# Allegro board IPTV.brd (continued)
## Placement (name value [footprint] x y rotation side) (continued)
R595  RC0402JR_070R  [R0402]  106.44 77.02 0 top
R596  RC0402JR_070R  [R0402]  106.44 78.17 0 top
R597  RC0402JR_070R  [R0402]  106.44 79.31 0 top
R598  RC0402JR_070R  [R0402]  106.44 80.45 0 top
R599  RC0402JR_070R  [R0402]  106.44 81.6 0 top
R600  RC0603JR_07510KL  [R0603]  91.07 78.93 180 top
R603  NI/RC0402JR_070R  [R0402]  156.19 54.24 180 top
R604  NI/RC0402JR_070R  [R0402]  156.19 52.97 180 top
R605  RCR0402JR_074K7  [R0402]  122.15 105.57 0 top
R606  RCR0402JR_074K7  [R0402]  122.15 104.43 0 top
R607  RHS_03K2490FT  [R0603]  128.27 101.73 0 top
R608  RCR0402JR_074K7  [R0402]  152.29 36.64 90 top
R609  RCR0402JR_074K7  [R0402]  153.68 36.64 90 top
R610  RHS_03K2490FT  [R0603]  156.06 45.76 0 top
R611  RCR0402JR_074K7  [R0402]  150.22 36.61 0 bottom
R612  RCR0402JR_074K7  [R0402]  153.39 34.07 90 bottom
R613  RHS_03K2490FT  [R0603]  144.76 32.8 180 bottom
R614  RCR0402JR_074K7  [R0402]  100.4 120.97 270 bottom
R615  RCR0402JR_074K7  [R0402]  99.25 120.97 270 bottom
R616  RHS_03K2490FT  [R0603]  96.62 118.66 90 top
R617  RK73B1ETTP330J  [R0402]  45.85 47.37 180 top
R618  RK73B1ETTP330J  [R0402]  30.58 40.93 0 bottom
R619  NC  [R0402]  36.84 20.25 270 bottom
R620  RC0402JR_070R  [R0402]  38.48 20.7 180 bottom
R621  NI/RC0402JR_070R  [R0402]  156.06 26.05 180 top
R622  RK73H1JTTD1001F  [R0603]  36.83 34.42 270 bottom
R623  RK73H1JTTD1001F  [R0603]  38.1 34.42 90 bottom
R624  RK73H1JTTD1001F  [R0603]  30.23 43.05 90 bottom
R625  RK73H1JTTD1001F  [R0603]  31.09 45.38 0 bottom
R626  NC  [R0402]  41.02 52.17 270 top
R627  NC  [R0402]  39.88 52.17 90 top
R628  NC  [R0402]  39.88 54.28 270 top
R629  NC  [R0402]  41.02 54.28 90 top
R630  NI/RC0402JR_070R  [R0402]  156.06 24.78 180 top
R631  RK73H1JTTD2000F  [R0603]  38.48 53.21 270 top
R632  NC/0R/0805  [R0805]  131.44 106.43 270 top
R633  NC/0R/0805  [R0805]  153.01 42.46 270 bottom
R634  RK73H1JTTD1001F  [R0603]  55.31 16.32 180 bottom
R635  RK73B1ETTP330J  [R0402]  43.92 6.26 0 bottom
R636  NC  [R0402]  37.85 25.65 270 bottom
R637  RC0402JR_070R  [R0402]  38.99 25.65 90 bottom
R638  RK73B1ETTP330J  [R0402]  38.48 19.43 0 bottom
R639  RK73H1JTTD1001F  [R0603]  51.85 5.27 180 bottom
R640  RK73H1JTTD1001F  [R0603]  51.85 6.54 0 bottom
R641  NC  [R0402]  42.16 21.97 0 top
R642  NC  [R0402]  42.16 20.83 180 top
R643  NC  [R0402]  40.13 20.83 0 top
R644  NC  [R0402]  40.13 21.97 180 top
R645  RK73H1JTTD2000F  [R0603]  41.15 19.56 0 top
R646  RK73H1JTTD1001F  [R0603]  55.31 17.59 0 bottom
R647  RC0603JR_0747K  [R0603]  38.23 21.97 0 bottom
R648  RC0603JR_0739K  [R0603]  38.23 23.62 0 bottom
R649  NC/0R/0805  [R0805]  148.82 34.2 0 top
R650  NC/0R/0805  [R0805]  99.54 117.64 180 bottom
REF*  VAL*  [unnamed#2]  160 102 0 top
REF*#2  VAL*  [unnamed#2]  9 102 0 top
REF*#3  VAL*  [unnamed#2]  160 12 0 top
REF*#4  VAL*  [unnamed#2]  9 12 0 top
T2  MMBT2222A  [SOT23_2]  99.72 91.75 90 top
T3  MMBT2222A  [SOT23_2]  107.29 12.86 270 top
T4  MMBT2222A  [SOT23_2]  123.44 9.65 180 top
T5  MMBT2222A  [SOT23_2]  127.36 9.94 0 bottom
T6  MMBT2222A  [SOT23_2]  99.92 12.74 270 top
T7  MMBT2222A  [SOT23_2]  9.75 59.47 90 top
T8  MMBT2222A  [SOT23_2]  109.32 92.87 270 bottom
T9  MMBT2222A  [SOT23_2]  14.96 32.3 0 bottom
TP1  -  [TP_SMD]  94.72 49.19 0 top
TP6  -  [TP_SMD]  135.36 90.08 0 top
TP7  -  [TP_SMD]  148.84 91.95 0 top
TP10  -  [TP_050M]  56.74 70.4 90 top
TP11  -  [TP_050M]  45.06 67.22 0 top
TP16  -  [TP_SMD]  128.14 79.88 0 top
TP19  -  [TP_SMD]  76.68 5.88 0 top
TP20  -  [TP_SMD]  77.45 10.32 0 top
TP29  -  [TP_SMD]  19.91 74.08 0 top
TP30  -  [TP_25]  90.02 101.38 0 top
TP31  -  [TP_25]  91.29 101.38 0 top
TP33  -  [TP_25]  30.58 84.62 0 top
TR2  H1606DG  [DIP-16]  23.37 100.71 270 top
U1  UPD720114GA_9BU_A  [QFP-9X9-48P-0_5S1]  98.56 77.91 270 top
U2  30M/3225  [OSC-3_2X2_5-4P]  88.15 75.88 270 top
U3  SRV05-4TCT  [SOT-23-6P]  116.46 113.28 90 bottom
U4  SRV05-4TCT  [SOT-23-6P]  159.11 38.77 0 bottom
U5  MIC2544_2BMMTR  [SO-4_9X3-8P-0_65]  126.75 104.39 180 top
U6  MIC2544_2BMMTR  [SO-4_9X3-8P-0_65]  153.81 41.72 270 top
U7  MIC2544_2BMMTR  [SO-4_9X3-8P-0_65]  149.43 34.16 0 bottom
U8  MIC2544_2BMMTR  [SO-4_9X3-8P-0_65]  99.16 118.91 90 top
U9  H5TQ1G63BFR_H9C  [CSP-14X10-96P-0_8]  37.72 41.4 90 top
U10  H5TQ1G63BFR_H9C  [CSP-14X10-96P-0_8]  48.51 11.81 180 top
U11  W25X16AVSSIG  [SO-7_9X5_2-8P-1_27]  91.82 55.12 270 top
U12  SIMMM12S2  [XS_SD_2041353_4]  26.95 36.12 270 top
U13  LM1117-ADJ  [SOT-223-4P]  53.57 73.82 90 top
U14  SRV05-4TCT  [SOT-23-6P]  47.24 110.74 180 bottom
U15  AZ1045-04F  [DFN-2_5X1-10P-0_5]  40.51 111.89 270 bottom
U16  AZ1045-04F  [DFN-2_5X1-10P-0_5]  42.16 115.06 0 bottom
U17  SRV05-4TCT  [SOT-23-6P]  23.62 92.2 90 bottom
U18  U/BCM43217KMLG/QFN68  [QFN-8X8-69P-0_4]  123.64 45.61 270 top
U19  U/RTC6603/SC70-6  [SC70-6P]  121.26 30.14 90 top
U20  SG809 2.63V  [SOT-23-3P]  74.52 11.21 0 top
U21  U/RTC6603/SC70-6  [SC70-6P]  130.91 30.39 180 top
U22  SGM8903  [SO-6_3X5-14P-0_65]  70.27 103.67 0 top
U23  U/PAM2305CGFADJ/PAM/QFN3X3  [DFN-2X2-7P-0_65S1]  112.66 41.03 270 bottom
U24  U/RT9166-12GVL/SOT23-3  [SOT-23-3P]  136.88 55.79 270 top
XL1  JA54-24MHZ(S)  [XL_HC_49U]  83.92 16.17 0 top
XP1  HDMI-SMT  [XP_HDMI_SMT]  40 119.4 180 top
XP2  TH-CNT-SX2.5-2P  [XP_2X1_100]  154.81 97.16 270 top
XS1  1064-00444  [USB-11153S1-13_6X14]  166.6 53.57 270 top
XS2  DC-2.0  [XS_DC_2_0]  144.5 117.79 270 top
XS4  1064-00444  [XS_USB_AF_4P]  108 116.3 270 top
XS5  1064-00444  [XS_USB_AF_4P]  125 116.3 270 top
XS7  DLT1150  [XS_DLT1150]  26.63 120.19 0 top
XS9  RCA-314-110  [XS_AV3_RCA_314]  91.25 118.4 180 top
XS10  1064-00444  [USB-11153S1-13_6X14]  166.6 25.42 270 top
XS11  <Value>  [RJ45-17_6X15-8PS1]  13.78 122.53 0 top
Y4  XTAL/20MHz/10ppm/8Z20070010  [OSC-3_2X2_5-4P]  136.12 44.11 90 top

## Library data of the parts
ANT1-ANT4 = ANT_0
ANT5 ANT6 = ANT_1
C1-C17 C19-C25 C35 C38-C42 C56-C59 C61 C67 C106 C122 C125 C128 C130-C133 C135 C138 C139 C142 C145 C147 C150 C154-C159 C162 C173 C175 C177 C180 C186 C196 C198 C200 C201 C275-C296 C298-C306 C309-C315 C392 C394 C404-C424 C426 C427 C429-C431 C433-C435 C437-C439 C441-C497 C0603 = C_0402
C18 = C_1206
C26 C28 C30 C31 C48 C63 C72 C178 C197 C199 = C_0805
C27 C29 = C_1210
C32 C33 C36 C37 C47 = CAPACITOR POL_0
C34 C60 C62 C268 C393 = C
C43-C46 C49-C52 C77-C82 C84-C98 C100 C102 C107-C109 C111-C121 C123 C124 C127 C134 C136 C137 C143 C144 C146 C148 C149 C151-C153 C160 C161 C163 C165 C167 C169 C171 C174 C176 C181 C182 C202 C205 C207-C209 C212-C217 C219-C223 C225-C227 C229-C237 C239 C243 C247 C251 C255 C297 C308 C341 C347-C354 C380-C384 = C_0603
C53 = C_2
C75 = C_0
C110 C126 C346 C425 C428 C432 C436 = CAP-X1
C193 C194 C224 C228 C238 C240-C242 C244-C246 C248-C250 C254 C316-C337 C339 C340 C342-C344 C355-C361 C364-C368 C370-C379 C385-C390 = CAP NP_5
C203 = CP_0
C210 C211 = 100nF_0402
C218 C345 C362 C363 C369 = CAP NP_0
C272 C274 = CAPACITOR NON-POL
C307 CAP3 = CAP_X
C338 C391 = C_1
D5 D6 = D_A_0
D10 D11 L23 R4-R6 R8-R10 R12 R15 R19 R28 R36-R87 R89 R91-R100 R102-R110 R112-R132 R134 R135 R138-R155 R157 R163-R173 R176-R178 R253-R255 R271 R273 R276 R290 R298-R316 R322 R329-R331 R354 R355 R365 R367 R368 R410 R414 R457 R458 R472-R475 R509 R563 R567 R583-R600 R603-R616 R621 R630 R632 R633 R649 R650 = R_0603
D16 = BAV99
D20 = BAV99_0
D37 = TSOP34338
FB1-FB4 L11 L12 L14 L15 L19 L25 L29 = L_0805
IC2 = NAND01GW3B2CN5E
IC5 IC26 = SOP14_065_440_640M_EXP
IC8 = IC12
IC9 = NCS2553DG
IC12 IC14 = MP1482DS
IC13 = HI3716C
IC17 = MP1484EN-LF-Z
JP1 = CN_5P-1_3
L1-L3 L5-L8 L10 L16 L18 L20-L22 L24 L34-L38 L41 L45 L46 = L_0603
L26 L31 L39 L40 L42 L44 = IND_1
L43 = INDUCTOR IRON
L47-L51 L55-L57 = L_0402
LED1 = LED_0805
LED5 LED12 = LED_0603
LED8 = LED_D4_2-2_54
LED10 LED11 = 209SURSYGW-S530
MARK1-MARK6 = MARK
Q5-Q10 = PWRMOSFET_EP_DGS_0
R7 R16 R18 R88 R90 R136 R137 R257 R317 R358 R359 R361 = R
R17 R133 R175 R188-R221 R231 R259-R270 R272 R274 R275 R277-R289 R360 R362 R617-R620 R622-R629 R631 R634-R648 = R_0402
R20 R29 R174 R252 R256 R318-R321 R323-R328 R332-R353 R356 R357 R397 = R_0
R101 R111 R160 R222-R230 R232 R233 R237 R240-R242 R244 R245 R248-R251 R292-R297 R363 R364 R366 R479 R485 = R_0805
R186 R187 = RESISTOR SIP 2
R234-R236 R238 R239 = R_0805: signal model: RESISTOR_SMD_RC0S00108_R0603_SB__
R246 = R_2
R247 = R_1
R258 = R_7
T2-T9 = MMBT2222A
TP1 TP6 TP7 TP10 TP11 TP16 TP19 TP20 TP29 = TP_30
TP30 TP31 TP33 = TP_25
TR2 = TR1
U1 = UPD720114GA_9BU_A
U2 = Q22FA2380008201
U3 U4 U14 U17 = SRV05-4TCT_1
U5-U8 = MIC2544_2BMMTR
U9 U10 = H5TQ1G63BFR_H9C
U11 = TMP75_1
U12 = SIMMM12S2_0
U13 = LM1117
U15 U16 = AZ1045-04F
U18 = U/BCM43217KMLG/QFN68_0
U19 U21 = U/RTC6603/SC70-6_1
U20 = ADM809_3
U22 = SGM8903_0
U23 = U/PAM2305CGFADJ/PAM/QFN3X3
U24 = U/RT9166-12GVL/SOT23-3
XL1 = XM/SM
XP1 = HDMI-SMT
XP2 = CN_2P-5A
XS1 = 1064-00444_0
XS2 = CN_3P-2_0
XS4 XS5 = 1064-00444
XS7 = DLT1150
XS9 = RCA-314-110
XS10 = 1064-00444_1
XS11 = RJ45_15X13-8PS1
Y4 = CRYSTAL_GND_1

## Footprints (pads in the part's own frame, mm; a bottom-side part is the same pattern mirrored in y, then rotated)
ANT-34X5-2P
  round 1.702 hole 1.092: 1(-10.162,0.182)
  oval 2.362x1.27 hole 1.6x0.508: 2(10.438,0.182)
BGA756_080M_38X38
  round 0.4 smd: A1(-14.8,14.8) A2(-14,14.8) A4(-12.4,14.8) A5(-11.6,14.8) A7(-10,14.8) A8(-9.2,14.8) A10(-7.6,14.8) A11(-6.8,14.8) A13(-5.2,14.8) A14(-4.4,14.8) A16(-2.8,14.8) A17(-2,14.8) A19(-0.4,14.8) A20(0.4,14.8) A22(2,14.8) A23(2.8,14.8) A25(4.4,14.8) A26(5.2,14.8) A28(6.8,14.8) A29(7.6,14.8) A31(9.2,14.8) A32(10,14.8) A34(11.6,14.8) A35(12.4,14.8) A37(14,14.8) A38(14.8,14.8) AA3(-13.2,-1.2) AA4(-12.4,-1.2) AA10(-7.6,-1.2) AA11(-6.8,-1.2) AA14(-4.4,-1.2) AA15(-3.6,-1.2) AA16(-2.8,-1.2) AA17(-2,-1.2) AA18(-1.2,-1.2) AA19(-0.4,-1.2) AA20(0.4,-1.2) AA21(1.2,-1.2) AA22(2,-1.2) AA23(2.8,-1.2) AA24(3.6,-1.2) AA25(4.4,-1.2) AA28(6.8,-1.2) AA29(7.6,-1.2) AA35(12.4,-1.2) AA36(13.2,-1.2) AB1(-14.8,-2) AB2(-14,-2) AB3(-13.2,-2) AB4(-12.4,-2) AB10(-7.6,-2) AB11(-6.8,-2) AB14(-4.4,-2) AB15(-3.6,-2) AB16(-2.8,-2) AB17(-2,-2) AB18(-1.2,-2) AB19(-0.4,-2) AB20(0.4,-2) AB21(1.2,-2) AB22(2,-2) AB23(2.8,-2) AB24(3.6,-2) AB25(4.4,-2) AB28(6.8,-2) AB29(7.6,-2) AB35(12.4,-2) AB36(13.2,-2) AB37(14,-2) AB38(14.8,-2) AC1(-14.8,-2.8) AC2(-14,-2.8) AC3(-13.2,-2.8) AC4(-12.4,-2.8) AC10(-7.6,-2.8) AC11(-6.8,-2.8) AC14(-4.4,-2.8) AC15(-3.6,-2.8) AC16(-2.8,-2.8) AC17(-2,-2.8) AC18(-1.2,-2.8) AC19(-0.4,-2.8) AC20(0.4,-2.8) AC21(1.2,-2.8) AC22(2,-2.8) AC23(2.8,-2.8) AC24(3.6,-2.8) AC25(4.4,-2.8) AC28(6.8,-2.8) AC29(7.6,-2.8) AC35(12.4,-2.8) AC36(13.2,-2.8) AC37(14,-2.8) AC38(14.8,-2.8) AD3(-13.2,-3.6) AD4(-12.4,-3.6) AD10(-7.6,-3.6) AD11(-6.8,-3.6) AD14(-4.4,-3.6) AD15(-3.6,-3.6) AD16(-2.8,-3.6) AD17(-2,-3.6) AD18(-1.2,-3.6) AD19(-0.4,-3.6) AD20(0.4,-3.6) AD21(1.2,-3.6) AD22(2,-3.6) AD23(2.8,-3.6) AD24(3.6,-3.6) AD25(4.4,-3.6) AD28(6.8,-3.6) AD29(7.6,-3.6) AD35(12.4,-3.6) AD36(13.2,-3.6) AE1(-14.8,-4.4) AE2(-14,-4.4) AE3(-13.2,-4.4) AE4(-12.4,-4.4) AE10(-7.6,-4.4) AE11(-6.8,-4.4) AE14(-4.4,-4.4) AE15(-3.6,-4.4) AE16(-2.8,-4.4) AE17(-2,-4.4) AE18(-1.2,-4.4) AE19(-0.4,-4.4) AE20(0.4,-4.4) AE21(1.2,-4.4) AE22(2,-4.4) AE23(2.8,-4.4) AE24(3.6,-4.4) AE25(4.4,-4.4) AE28(6.8,-4.4) AE29(7.6,-4.4) AE35(12.4,-4.4) AE36(13.2,-4.4) AE37(14,-4.4) AE38(14.8,-4.4) AF1(-14.8,-5.2) AF2(-14,-5.2) AF3(-13.2,-5.2) AF4(-12.4,-5.2) AF10(-7.6,-5.2) AF11(-6.8,-5.2) AF28(6.8,-5.2) AF29(7.6,-5.2) AF35(12.4,-5.2) AF36(13.2,-5.2) AF37(14,-5.2) AF38(14.8,-5.2) AG3(-13.2,-6) AG4(-12.4,-6) AG10(-7.6,-6) AG11(-6.8,-6) AG28(6.8,-6) AG29(7.6,-6) AG35(12.4,-6) AG36(13.2,-6) AH1(-14.8,-6.8) AH2(-14,-6.8) AH3(-13.2,-6.8) AH4(-12.4,-6.8) AH10(-7.6,-6.8) AH11(-6.8,-6.8) AH12(-6,-6.8) AH13(-5.2,-6.8) AH14(-4.4,-6.8) AH15(-3.6,-6.8) AH16(-2.8,-6.8) AH17(-2,-6.8) AH18(-1.2,-6.8) AH19(-0.4,-6.8) AH20(0.4,-6.8) AH21(1.2,-6.8) AH22(2,-6.8) AH23(2.8,-6.8) AH24(3.6,-6.8) AH25(4.4,-6.8) AH26(5.2,-6.8) AH27(6,-6.8) AH28(6.8,-6.8) AH29(7.6,-6.8) AH35(12.4,-6.8) AH36(13.2,-6.8) AH37(14,-6.8) AH38(14.8,-6.8) AJ1(-14.8,-7.6) AJ2(-14,-7.6) AJ3(-13.2,-7.6) AJ4(-12.4,-7.6) AJ10(-7.6,-7.6) AJ11(-6.8,-7.6) AJ12(-6,-7.6) AJ13(-5.2,-7.6) AJ14(-4.4,-7.6) AJ15(-3.6,-7.6) AJ16(-2.8,-7.6) AJ17(-2,-7.6) AJ18(-1.2,-7.6) AJ19(-0.4,-7.6) AJ20(0.4,-7.6) AJ21(1.2,-7.6) AJ22(2,-7.6) AJ23(2.8,-7.6) AJ24(3.6,-7.6) AJ25(4.4,-7.6) AJ26(5.2,-7.6) AJ27(6,-7.6) AJ28(6.8,-7.6) AJ29(7.6,-7.6) AJ35(12.4,-7.6) AJ36(13.2,-7.6) AJ37(14,-7.6) AJ38(14.8,-7.6) AK3(-13.2,-8.4) AK4(-12.4,-8.4) AK35(12.4,-8.4) AK36(13.2,-8.4) AL1(-14.8,-9.2) AL2(-14,-9.2) AL3(-13.2,-9.2) AL4(-12.4,-9.2) AL35(12.4,-9.2) AL36(13.2,-9.2) AL37(14,-9.2) AL38(14.8,-9.2) AM1(-14.8,-10) AM2(-14,-10) AM3(-13.2,-10) AM4(-12.4,-10) AM35(12.4,-10) AM36(13.2,-10) AM37(14,-10) AM38(14.8,-10) AN3(-13.2,-10.8) AN4(-12.4,-10.8) AN5(-11.6,-10.8) AN34(11.6,-10.8) AN35(12.4,-10.8) AN36(13.2,-10.8) AP1(-14.8,-11.6) AP2(-14,-11.6) AP3(-13.2,-11.6) AP4(-12.4,-11.6) AP5(-11.6,-11.6) AP6(-10.8,-11.6) AP33(10.8,-11.6) AP34(11.6,-11.6) AP35(12.4,-11.6) AP36(13.2,-11.6) AP37(14,-11.6) AP38(14.8,-11.6) AR1(-14.8,-12.4) AR2(-14,-12.4) AR3(-13.2,-12.4) AR4(-12.4,-12.4) AR5(-11.6,-12.4) AR6(-10.8,-12.4) AR7(-10,-12.4) AR8(-9.2,-12.4) AR9(-8.4,-12.4) AR10(-7.6,-12.4) AR11(-6.8,-12.4) AR12(-6,-12.4) AR13(-5.2,-12.4) AR14(-4.4,-12.4) AR15(-3.6,-12.4) AR16(-2.8,-12.4) AR17(-2,-12.4) AR18(-1.2,-12.4) AR19(-0.4,-12.4) AR20(0.4,-12.4) AR21(1.2,-12.4) AR22(2,-12.4) AR23(2.8,-12.4) AR24(3.6,-12.4) AR25(4.4,-12.4) AR26(5.2,-12.4) AR27(6,-12.4) AR28(6.8,-12.4) AR29(7.6,-12.4) AR30(8.4,-12.4) AR31(9.2,-12.4) AR32(10,-12.4) AR33(10.8,-12.4) AR34(11.6,-12.4) AR35(12.4,-12.4) AR36(13.2,-12.4) AR37(14,-12.4) AR38(14.8,-12.4) AT2(-14,-13.2) AT3(-13.2,-13.2) AT4(-12.4,-13.2) AT5(-11.6,-13.2) AT6(-10.8,-13.2) AT7(-10,-13.2) AT8(-9.2,-13.2) AT9(-8.4,-13.2) AT10(-7.6,-13.2) AT11(-6.8,-13.2) AT12(-6,-13.2) AT13(-5.2,-13.2) AT14(-4.4,-13.2) AT15(-3.6,-13.2) AT16(-2.8,-13.2) AT17(-2,-13.2) AT18(-1.2,-13.2) AT19(-0.4,-13.2) AT20(0.4,-13.2) AT21(1.2,-13.2) AT22(2,-13.2) AT23(2.8,-13.2) AT24(3.6,-13.2) AT25(4.4,-13.2) AT26(5.2,-13.2) AT27(6,-13.2) AT28(6.8,-13.2) AT29(7.6,-13.2) AT30(8.4,-13.2) AT31(9.2,-13.2) AT32(10,-13.2) AT33(10.8,-13.2) AT34(11.6,-13.2) AT35(12.4,-13.2) AT36(13.2,-13.2) AT37(14,-13.2) AU1(-14.8,-14) AU2(-14,-14) AU3(-13.2,-14) AU4(-12.4,-14) AU5(-11.6,-14) AU7(-10,-14) AU8(-9.2,-14) AU10(-7.6,-14) AU11(-6.8,-14) AU13(-5.2,-14) AU14(-4.4,-14) AU16(-2.8,-14) AU17(-2,-14) AU19(-0.4,-14) AU20(0.4,-14) AU22(2,-14) AU23(2.8,-14) AU25(4.4,-14) AU26(5.2,-14) AU28(6.8,-14) AU29(7.6,-14) AU31(9.2,-14) AU32(10,-14) AU34(11.6,-14) AU35(12.4,-14) AU36(13.2,-14) AU37(14,-14) AU38(14.8,-14) AV1(-14.8,-14.8) AV2(-14,-14.8) AV4(-12.4,-14.8) AV5(-11.6,-14.8) AV7(-10,-14.8) AV8(-9.2,-14.8) AV10(-7.6,-14.8) AV11(-6.8,-14.8) AV13(-5.2,-14.8) AV14(-4.4,-14.8) AV16(-2.8,-14.8) AV17(-2,-14.8) AV19(-0.4,-14.8) AV20(0.4,-14.8) AV22(2,-14.8) AV23(2.8,-14.8) AV25(4.4,-14.8) AV26(5.2,-14.8) AV28(6.8,-14.8) AV29(7.6,-14.8) AV31(9.2,-14.8) AV32(10,-14.8) AV34(11.6,-14.8) AV35(12.4,-14.8) AV37(14,-14.8) AV38(14.8,-14.8) B1(-14.8,14) B2(-14,14) B3(-13.2,14) B4(-12.4,14) B5(-11.6,14) B7(-10,14) B8(-9.2,14) B10(-7.6,14) B11(-6.8,14) B13(-5.2,14) B14(-4.4,14) B16(-2.8,14) B17(-2,14) B19(-0.4,14) B20(0.4,14) B22(2,14) B23(2.8,14) B25(4.4,14) B26(5.2,14) B28(6.8,14) B29(7.6,14) B31(9.2,14) B32(10,14) B34(11.6,14) B35(12.4,14) B36(13.2,14) B37(14,14) B38(14.8,14) C2(-14,13.2) C3(-13.2,13.2) C4(-12.4,13.2) C5(-11.6,13.2) C6(-10.8,13.2) C7(-10,13.2) C8(-9.2,13.2) C9(-8.4,13.2) C10(-7.6,13.2) C11(-6.8,13.2) C12(-6,13.2) C13(-5.2,13.2) C14(-4.4,13.2) C15(-3.6,13.2) C16(-2.8,13.2) C17(-2,13.2) C18(-1.2,13.2) C19(-0.4,13.2) C20(0.4,13.2) C21(1.2,13.2) C22(2,13.2) C23(2.8,13.2) C24(3.6,13.2) C25(4.4,13.2) C26(5.2,13.2) C27(6,13.2) C28(6.8,13.2) C29(7.6,13.2) C30(8.4,13.2) C31(9.2,13.2) C32(10,13.2) C33(10.8,13.2) C34(11.6,13.2) C35(12.4,13.2) C36(13.2,13.2) C37(14,13.2) D1(-14.8,12.4) D2(-14,12.4) D3(-13.2,12.4) D4(-12.4,12.4) D5(-11.6,12.4) D6(-10.8,12.4) D7(-10,12.4) D8(-9.2,12.4) D9(-8.4,12.4) D10(-7.6,12.4) D11(-6.8,12.4) D12(-6,12.4) D13(-5.2,12.4) D14(-4.4,12.4) D15(-3.6,12.4) D16(-2.8,12.4) D17(-2,12.4) D18(-1.2,12.4) D19(-0.4,12.4) D20(0.4,12.4) D21(1.2,12.4) D22(2,12.4) D23(2.8,12.4) D24(3.6,12.4) D25(4.4,12.4) D26(5.2,12.4) D27(6,12.4) D28(6.8,12.4) D29(7.6,12.4) D30(8.4,12.4) D31(9.2,12.4) D32(10,12.4) D33(10.8,12.4) D34(11.6,12.4) D35(12.4,12.4) D36(13.2,12.4) D37(14,12.4) D38(14.8,12.4) E1(-14.8,11.6) E2(-14,11.6) E3(-13.2,11.6) E4(-12.4,11.6) E5(-11.6,11.6) E6(-10.8,11.6) E33(10.8,11.6) E34(11.6,11.6) E35(12.4,11.6) E36(13.2,11.6) E37(14,11.6) E38(14.8,11.6) F3(-13.2,10.8) F4(-12.4,10.8) F5(-11.6,10.8) F34(11.6,10.8) F35(12.4,10.8) F36(13.2,10.8) G1(-14.8,10) G2(-14,10) G3(-13.2,10) G4(-12.4,10) G35(12.4,10) G36(13.2,10) G37(14,10) G38(14.8,10) H1(-14.8,9.2) H2(-14,9.2) H3(-13.2,9.2) H4(-12.4,9.2) H35(12.4,9.2) H36(13.2,9.2) H37(14,9.2) H38(14.8,9.2) J3(-13.2,8.4) J4(-12.4,8.4) J35(12.4,8.4) J36(13.2,8.4) K1(-14.8,7.6) K2(-14,7.6) K3(-13.2,7.6) K4(-12.4,7.6) K10(-7.6,7.6) K11(-6.8,7.6) K12(-6,7.6) K13(-5.2,7.6) K14(-4.4,7.6) K15(-3.6,7.6) K16(-2.8,7.6) K17(-2,7.6) K18(-1.2,7.6) K19(-0.4,7.6) K20(0.4,7.6) K21(1.2,7.6) K22(2,7.6) K23(2.8,7.6) K24(3.6,7.6) K25(4.4,7.6) K26(5.2,7.6) K27(6,7.6) K28(6.8,7.6) K29(7.6,7.6) K35(12.4,7.6) K36(13.2,7.6) K37(14,7.6) K38(14.8,7.6) L1(-14.8,6.8) L2(-14,6.8) L3(-13.2,6.8) L4(-12.4,6.8) L10(-7.6,6.8) L11(-6.8,6.8) L12(-6,6.8) L13(-5.2,6.8) L14(-4.4,6.8) L15(-3.6,6.8) L16(-2.8,6.8) L17(-2,6.8) L18(-1.2,6.8) L19(-0.4,6.8) L20(0.4,6.8) L21(1.2,6.8) L22(2,6.8) L23(2.8,6.8) L24(3.6,6.8) L25(4.4,6.8) L26(5.2,6.8) L27(6,6.8) L28(6.8,6.8) L29(7.6,6.8) L35(12.4,6.8) L36(13.2,6.8) L37(14,6.8) L38(14.8,6.8) M3(-13.2,6) M4(-12.4,6) M10(-7.6,6) M11(-6.8,6) M28(6.8,6) M29(7.6,6) M35(12.4,6) M36(13.2,6) N1(-14.8,5.2) N2(-14,5.2) N3(-13.2,5.2) N4(-12.4,5.2) N10(-7.6,5.2) N11(-6.8,5.2) N28(6.8,5.2) N29(7.6,5.2) N35(12.4,5.2) N36(13.2,5.2) N37(14,5.2) N38(14.8,5.2) P1(-14.8,4.4) P2(-14,4.4) P3(-13.2,4.4) P4(-12.4,4.4) P10(-7.6,4.4) P11(-6.8,4.4) P14(-4.4,4.4) P15(-3.6,4.4) P16(-2.8,4.4) P17(-2,4.4) P18(-1.2,4.4) P19(-0.4,4.4) P20(0.4,4.4) P21(1.2,4.4) P22(2,4.4) P23(2.8,4.4) P24(3.6,4.4) P25(4.4,4.4) P28(6.8,4.4) P29(7.6,4.4) P35(12.4,4.4) P36(13.2,4.4) P37(14,4.4) P38(14.8,4.4) R3(-13.2,3.6) R4(-12.4,3.6) R10(-7.6,3.6) R11(-6.8,3.6) R14(-4.4,3.6) R15(-3.6,3.6) R16(-2.8,3.6) R17(-2,3.6) R18(-1.2,3.6) R19(-0.4,3.6) R20(0.4,3.6) R21(1.2,3.6) R22(2,3.6) R23(2.8,3.6) R24(3.6,3.6) R25(4.4,3.6) R28(6.8,3.6) R29(7.6,3.6) R35(12.4,3.6) R36(13.2,3.6) T1(-14.8,2.8) T2(-14,2.8) T3(-13.2,2.8) T4(-12.4,2.8) T10(-7.6,2.8) T11(-6.8,2.8) T14(-4.4,2.8) T15(-3.6,2.8) T16(-2.8,2.8) T17(-2,2.8) T18(-1.2,2.8) T19(-0.4,2.8) T20(0.4,2.8) T21(1.2,2.8) T22(2,2.8) T23(2.8,2.8) T24(3.6,2.8) T25(4.4,2.8) T28(6.8,2.8) T29(7.6,2.8) T35(12.4,2.8) T36(13.2,2.8) T37(14,2.8) T38(14.8,2.8) U1(-14.8,2) U2(-14,2) U3(-13.2,2) U4(-12.4,2) U10(-7.6,2) U11(-6.8,2) U14(-4.4,2) U15(-3.6,2) U16(-2.8,2) U17(-2,2) U18(-1.2,2) U19(-0.4,2) U20(0.4,2) U21(1.2,2) U22(2,2) U23(2.8,2) U24(3.6,2) U25(4.4,2) U28(6.8,2) U29(7.6,2) U35(12.4,2) U36(13.2,2) U37(14,2) U38(14.8,2) V3(-13.2,1.2) V4(-12.4,1.2) V10(-7.6,1.2) V11(-6.8,1.2) V14(-4.4,1.2) V15(-3.6,1.2) V16(-2.8,1.2) V17(-2,1.2) V18(-1.2,1.2) V19(-0.4,1.2) V20(0.4,1.2) V21(1.2,1.2) V22(2,1.2) V23(2.8,1.2) V24(3.6,1.2) V25(4.4,1.2) V28(6.8,1.2) V29(7.6,1.2) V35(12.4,1.2) V36(13.2,1.2) W1(-14.8,0.4) W2(-14,0.4) W3(-13.2,0.4) W4(-12.4,0.4) W10(-7.6,0.4) W11(-6.8,0.4) W14(-4.4,0.4) W15(-3.6,0.4) W16(-2.8,0.4) W17(-2,0.4) W18(-1.2,0.4) W19(-0.4,0.4) W20(0.4,0.4) W21(1.2,0.4) W22(2,0.4) W23(2.8,0.4) W24(3.6,0.4) W25(4.4,0.4) W28(6.8,0.4) W29(7.6,0.4) W35(12.4,0.4) W36(13.2,0.4) W37(14,0.4) W38(14.8,0.4) Y1(-14.8,-0.4) Y2(-14,-0.4) Y3(-13.2,-0.4) Y4(-12.4,-0.4) Y10(-7.6,-0.4) Y11(-6.8,-0.4) Y14(-4.4,-0.4) Y15(-3.6,-0.4) Y16(-2.8,-0.4) Y17(-2,-0.4) Y18(-1.2,-0.4) Y19(-0.4,-0.4) Y20(0.4,-0.4) Y21(1.2,-0.4) Y22(2,-0.4) Y23(2.8,-0.4) Y24(3.6,-0.4) Y25(4.4,-0.4) Y28(6.8,-0.4) Y29(7.6,-0.4) Y35(12.4,-0.4) Y36(13.2,-0.4) Y37(14,-0.4) Y38(14.8,-0.4)
C0402
  rect 0.559x0.61 smd: 1(-0.483,0) 2(0.483,0)
C0603
  rect 0.762x0.762 smd: 1(-0.762,0) 2(0.762,0)
C0805
  rect 1.397x1.27 smd: 1(-1.206,0) 2(1.206,0)
C1206
  rect 1.778x1.778 smd: 1(-1.504,0) 2(1.504,0)
C1210
  rect 1.778x2.794 smd: 1(-1.854,0) 2(1.854,0)
C3216P
  rect 1.524x1.27 smd: 1(-1.625,0) 2(1.625,0)
C6032P
  rect 2.286x2.413 smd: 1(-2.921,0) 2(2.921,0)
C-D5XH11-2_5
  round 1.422 hole 0.813: 1(0,1.25) 2(0,-1.25)
C-D6-2_54
  round 1.422 hole 0.813: 1(0,1.27) 2(0,-1.27)
C-D6_3XH11-2_5
  round 1.422 hole 0.813: 1(0,1.25) 2(0,-1.25)
C-D6_3XH12-2_5
  round 1.626 hole 0.813: 1(0,1.25) 2(0,-1.25)
C_200_250
  rect 2x2 hole 1: 1(0,0)
  round 2 hole 1: 2(5.08,0)
C_250M_630X1200P
  rect 2x2 hole 1: 1(-1.25,0)
  round 2 hole 1: 2(1.25,0)
C_500M_1000X1500P
  rect 2.1x2.1 hole 1: 1(-2.5,0)
  round 2.1 hole 1: 2(2.5,0)
CSP-14X10-96P-0_8
  round 0.406 smd: A1(-6,-3.2) A2(-6,-2.4) A3(-6,-1.6) A7(-6,1.6) A8(-6,2.4) A9(-6,3.2) B1(-5.2,-3.2) B2(-5.2,-2.4) B3(-5.2,-1.6) B7(-5.2,1.6) B8(-5.2,2.4) B9(-5.2,3.2) C1(-4.4,-3.2) C2(-4.4,-2.4) C3(-4.4,-1.6) C7(-4.4,1.6) C8(-4.4,2.4) C9(-4.4,3.2) D1(-3.6,-3.2) D2(-3.6,-2.4) D3(-3.6,-1.6) D7(-3.6,1.6) D8(-3.6,2.4) D9(-3.6,3.2) E1(-2.8,-3.2) E2(-2.8,-2.4) E3(-2.8,-1.6) E7(-2.8,1.6) E8(-2.8,2.4) E9(-2.8,3.2) F1(-2,-3.2) F2(-2,-2.4) F3(-2,-1.6) F7(-2,1.6) F8(-2,2.4) F9(-2,3.2) G1(-1.2,-3.2) G2(-1.2,-2.4) G3(-1.2,-1.6) G7(-1.2,1.6) G8(-1.2,2.4) G9(-1.2,3.2) H1(-0.4,-3.2) H2(-0.4,-2.4) H3(-0.4,-1.6) H7(-0.4,1.6) H8(-0.4,2.4) H9(-0.4,3.2) J1(0.4,-3.2) J2(0.4,-2.4) J3(0.4,-1.6) J7(0.4,1.6) J8(0.4,2.4) J9(0.4,3.2) K1(1.2,-3.2) K2(1.2,-2.4) K3(1.2,-1.6) K7(1.2,1.6) K8(1.2,2.4) K9(1.2,3.2) L1(2,-3.2) L2(2,-2.4) L3(2,-1.6) L7(2,1.6) L8(2,2.4) L9(2,3.2) M1(2.8,-3.2) M2(2.8,-2.4) M3(2.8,-1.6) M7(2.8,1.6) M8(2.8,2.4) M9(2.8,3.2) N1(3.6,-3.2) N2(3.6,-2.4) N3(3.6,-1.6) N7(3.6,1.6) N8(3.6,2.4) N9(3.6,3.2) P1(4.4,-3.2) P2(4.4,-2.4) P3(4.4,-1.6) P7(4.4,1.6) P8(4.4,2.4) P9(4.4,3.2) R1(5.2,-3.2) R2(5.2,-2.4) R3(5.2,-1.6) R7(5.2,1.6) R8(5.2,2.4) R9(5.2,3.2) T1(6,-3.2) T2(6,-2.4) T3(6,-1.6) T7(6,1.6) T8(6,2.4) T9(6,3.2)
D-6_86X4_06
  rect 2.794x2.159 smd: 1(0,2.223) 2(0,-2.223)
D_LAMP_209SURSYGW
  rect 1.5x1.5 hole 0.8: 1(0,0)
  round 1.5 hole 0.8: 2(-2.54,0) 3(2.54,0)
D_TSOP34XXX
  rect 1.7x1.7 hole 1.1: 1(0,0)
  round 1.7 hole 1.1: 2(2.54,0) 3(5.08,0)
DFN-2_5X1-10P-0_5
  rect 0.254x0.686 smd: 1(-1,-0.448) 2(-0.5,-0.448) 4(0.5,-0.448) 5(1,-0.448) 6(1,0.448) 7(0.5,0.448) 9(-0.5,0.448) 10(-1,0.448)
  rect 0.356x0.762 smd: 3(0,-0.41) 8(0,0.41)
DFN-2X2-7P-0_65S1
  rect 0.61x0.356 smd: 1(1.025,-0.65) 2(1.025,0) 3(1.025,0.65) 4(-1.025,0.65) 5(-1.025,0) 6(-1.025,-0.65)
  rect 0.813x1.397 smd: 7(0,0)
DIP-16
  rect 1.397x1.397 hole 0.813: 1(3.81,-8.89)
  round 1.397 hole 0.813: 2(3.81,-6.35) 3(3.81,-3.81) 4(3.81,-1.27) 5(3.81,1.27) 6(3.81,3.81) 7(3.81,6.35) 8(3.81,8.89) 9(-3.81,8.89) 10(-3.81,6.35) 11(-3.81,3.81) 12(-3.81,1.27) 13(-3.81,-1.27) 14(-3.81,-3.81) 15(-3.81,-6.35) 16(-3.81,-8.89)
F-11_7X3-5_1-2P
  round 2.54 hole 1.016: 1(-2.55,-0.45) 2(2.55,0.45)
FILDMC_40
  round 1.016 smd: 1(0,0)
IND-0402
  rect 0.508x0.559 smd: 1(-0.406,0) 2(0.406,0)
JACK-COAXIAL-4P-NTPS1
  rect 0.991x1.524 smd: 1(0,1.779) 2(-1.475,-0.508) 3(1.475,-0.508)
  rect 3.962x2.032 smd: 4(0,-2.794)
JP_1X5_100
  rect 1.5x1.5 hole 1: 1(0,5.08)
  round 1.5 hole 1: 2(0,2.54) 3(0,0) 4(0,-2.54) 5(0,-5.08)
L0402
  custom 0.14x0.14 smd: 1(0,0.495) 2(0,-0.495)
L0603
  rect 0.762x0.762 smd: 1(-0.762,0) 2(0.762,0)
L0805
  rect 1.397x1.27 smd: 1(-1.27,0) 2(1.27,0)
L1206
  rect 1.803x1.016 smd: 1(0,1.52) 2(0,-1.52)
L1210
  rect 2.489x1.6 smd: 1(0,1.4) 2(0,-1.4)
L_DO3316
  rect 3.81x3.81 smd: 1(-5.08,0) 2(5.08,0)
LED0603
  rect 0.813x0.762 smd: 1(0,0.686) 2(0,-0.686)
LED_254M_3MM
  rect 2x2 hole 1.2: 1(0,0)
  round 2 hole 1.2: 2(2.54,0)
MLF32_050M
  rect 0.76x0.3 smd: 1(-2.425,1.75) 2(-2.425,1.25) 3(-2.425,0.75) 4(-2.425,0.25) 5(-2.425,-0.25) 6(-2.425,-0.75) 7(-2.425,-1.25) 8(-2.425,-1.75) 17(2.425,-1.75) 18(2.425,-1.25) 19(2.425,-0.75) 20(2.425,-0.25) 21(2.425,0.25) 22(2.425,0.75) 23(2.425,1.25) 24(2.425,1.75)
  rect 0.3x0.76 smd: 9(-1.75,-2.425) 10(-1.25,-2.425) 11(-0.75,-2.425) 12(-0.25,-2.425) 13(0.25,-2.425) 14(0.75,-2.425) 15(1.25,-2.425) 16(1.75,-2.425) 25(1.75,2.425) 26(1.25,2.425) 27(0.75,2.425) 28(0.25,2.425) 29(-0.25,2.425) 30(-0.75,2.425) 31(-1.25,2.425) 32(-1.75,2.425)
  rect 2.6x2.6 smd: 33(0,0)
OSC-3_2X2_5-4P
  rect 1.397x1.194 smd: 1(-1.151,-0.848) 2(1.151,-0.848) 3(1.151,0.848) 4(-1.151,0.848)
QFN-8X8-69P-0_4
  rect 0.203x0.813 smd: 1(-3.2,-3.9) 2(-2.8,-3.9) 3(-2.4,-3.9) 4(-2,-3.9) 5(-1.6,-3.9) 6(-1.2,-3.9) 7(-0.8,-3.9) 8(-0.4,-3.9) 9(0,-3.9) 10(0.4,-3.9) 11(0.8,-3.9) 12(1.2,-3.9) 13(1.6,-3.9) 14(2,-3.9) 15(2.4,-3.9) 16(2.8,-3.9) 17(3.2,-3.9) 35(3.2,3.9) 36(2.8,3.9) 37(2.4,3.9) 38(2,3.9) 39(1.6,3.9) 40(1.2,3.9) 41(0.8,3.9) 42(0.4,3.9) 43(0,3.9) 44(-0.4,3.9) 45(-0.8,3.9) 46(-1.2,3.9) 47(-1.6,3.9) 48(-2,3.9) 49(-2.4,3.9) 50(-2.8,3.9) 51(-3.2,3.9)
  rect 0.813x0.203 smd: 18(3.9,-3.2) 19(3.9,-2.8) 20(3.9,-2.4) 21(3.9,-2) 22(3.9,-1.6) 23(3.9,-1.2) 24(3.9,-0.8) 25(3.9,-0.4) 26(3.9,0) 27(3.9,0.4) 28(3.9,0.8) 29(3.9,1.2) 30(3.9,1.6) 31(3.9,2) 32(3.9,2.4) 33(3.9,2.8) 34(3.9,3.2) 52(-3.9,3.2) 53(-3.9,2.8) 54(-3.9,2.4) 55(-3.9,2) 56(-3.9,1.6) 57(-3.9,1.2) 58(-3.9,0.8) 59(-3.9,0.4) 60(-3.9,0) 61(-3.9,-0.4) 62(-3.9,-0.8) 63(-3.9,-1.2) 64(-3.9,-1.6) 65(-3.9,-2) 66(-3.9,-2.4) 67(-3.9,-2.8) 68(-3.9,-3.2)
  rect 5.588x6.02 smd: 69(0.187,0)
QFP-9X9-48P-0_5S1
  rect 1.016x1.016 smd: (-4.242,4.216) (4.242,-4.242)
  rect 0.254x1.524 smd: 1(-2.75,-4.244) 2(-2.25,-4.244) 3(-1.75,-4.244) 4(-1.25,-4.244) 5(-0.75,-4.244) 6(-0.25,-4.244) 7(0.25,-4.244) 8(0.75,-4.244) 9(1.25,-4.244) 10(1.75,-4.244) 11(2.25,-4.244) 12(2.75,-4.244) 25(2.75,4.244) 26(2.25,4.244) 27(1.75,4.244) 28(1.25,4.244) 29(0.75,4.244) 30(0.25,4.244) 31(-0.25,4.244) 32(-0.75,4.244) 33(-1.25,4.244) 34(-1.75,4.244) 35(-2.25,4.244) 36(-2.75,4.244)
  rect 1.524x0.254 smd: 13(4.244,-2.75) 14(4.244,-2.25) 15(4.244,-1.75) 16(4.244,-1.25) 17(4.244,-0.75) 18(4.244,-0.25) 19(4.244,0.25) 20(4.244,0.75) 21(4.244,1.25) 22(4.244,1.75) 23(4.244,2.25) 24(4.244,2.75) 37(-4.244,2.75) 38(-4.244,2.25) 39(-4.244,1.75) 40(-4.244,1.25) 41(-4.244,0.75) 42(-4.244,0.25) 43(-4.244,-0.25) 44(-4.244,-0.75) 45(-4.244,-1.25) 46(-4.244,-1.75) 47(-4.244,-2.25) 48(-4.244,-2.75)
R0402
  rect 0.559x0.61 smd: 1(-0.483,0) 2(0.483,0)
R0603
  rect 0.762x0.762 smd: 1(-0.762,0) 2(0.762,0)
R0805
  rect 1.397x1.27 smd: 1(-1.206,0) 2(1.206,0)
R1206
  rect 1.524x1.6 smd: 1(0,1.397) 2(0,-1.397)
R-7_4X3-5_1-2P
  round 1.524 hole 0.914: 1(-2.55,-1.5) 2(2.55,1.5)
RJ45-17_6X15-8PS1
  round 3.2 hole 3.2 unplated: (-5.715,1.171) (5.715,1.171)
  round 1.499 hole 0.889: A1(4.445,-5.179) A2(3.175,-7.719) A3(1.905,-5.179) A4(0.635,-7.719) A5(-0.635,-5.179) A6(-1.905,-7.719) A7(-3.175,-5.179) A8(-4.445,-7.719)
SC70-6P
  rect 0.762x0.406 smd: 1(0.965,-0.635) 2(0.965,0) 3(0.965,0.635) 4(-0.965,0.635) 5(-0.965,0) 6(-0.965,-0.635)
SO-4_9X3-8P-0_65
  rect 1.524x0.356 smd: 1(2.07,-0.975) 2(2.07,-0.325) 3(2.07,0.325) 4(2.07,0.975) 5(-2.07,0.975) 6(-2.07,0.325) 7(-2.07,-0.325) 8(-2.07,-0.975)
SO-6_3X5-14P-0_65
  rect 1.219x0.305 smd: 1(3,-1.95) 2(3,-1.3) 3(3,-0.65) 4(3,0) 5(3,0.65) 6(3,1.3) 7(3,1.95) 8(-3,1.95) 9(-3,1.3) 10(-3,0.65) 11(-3,0) 12(-3.005,-0.65) 13(-3,-1.3) 14(-3,-1.95)
SO-7_9X5_2-8P-1_27
  rect 2.032x0.635 smd: 1(3.556,-1.905) 2(3.556,-0.635) 3(3.556,0.635) 4(3.556,1.905) 5(-3.556,1.905) 6(-3.556,0.635) 7(-3.556,-0.635) 8(-3.556,-1.905)
SOP8_127_390_600M
  rect 1.69x0.76 smd: 1(-2.505,1.905) 2(-2.505,0.635) 3(-2.505,-0.635) 4(-2.505,-1.905) 5(2.505,-1.905) 6(2.505,-0.635) 7(2.505,0.635) 8(2.505,1.905)
SOP8_127_390_600M_EXP
  rect 1.55x0.76 smd: 1(-2.575,1.905) 2(-2.575,0.635) 3(-2.575,-0.635) 4(-2.575,-1.905) 5(2.575,-1.905) 6(2.575,-0.635) 7(2.575,0.635) 8(2.575,1.905)
  rect 2.4x3.1 smd: 9(0,0)
SOP14_065_440_640M_EXP
  rect 1.48x0.39 smd: 1(-2.81,1.95) 2(-2.81,1.3) 3(-2.81,0.65) 4(-2.81,0) 5(-2.81,-0.65) 6(-2.81,-1.3) 7(-2.81,-1.95) 8(2.81,-1.95) 9(2.81,-1.3) 10(2.81,-0.65) 11(2.81,0) 12(2.81,0.65) 13(2.81,1.3) 14(2.81,1.95)
  rect 2.6x2.6 smd: 15(0,0)
SOP48_050_1840_2000M
  rect 1.45x0.3 smd: 1(-9.625,5.75) 2(-9.625,5.25) 3(-9.625,4.75) 4(-9.625,4.25) 5(-9.625,3.75) 6(-9.625,3.25) 7(-9.625,2.75) 8(-9.625,2.25) 9(-9.625,1.75) 10(-9.625,1.25) 11(-9.625,0.75) 12(-9.625,0.25) 13(-9.625,-0.25) 14(-9.625,-0.75) 15(-9.625,-1.25) 16(-9.625,-1.75) 17(-9.625,-2.25) 18(-9.625,-2.75) 19(-9.625,-3.25) 20(-9.625,-3.75) 21(-9.625,-4.25) 22(-9.625,-4.75) 23(-9.625,-5.25) 24(-9.625,-5.75) 25(9.625,-5.75) 26(9.625,-5.25) 27(9.625,-4.75) 28(9.625,-4.25) 29(9.625,-3.75) 30(9.625,-3.25) 31(9.625,-2.75) 32(9.625,-2.25) 33(9.625,-1.75) 34(9.625,-1.25) 35(9.625,-0.75) 36(9.625,-0.25) 37(9.625,0.25) 38(9.625,0.75) 39(9.625,1.25) 40(9.625,1.75) 41(9.625,2.25) 42(9.625,2.75) 43(9.625,3.25) 44(9.625,3.75) 45(9.625,4.25) 46(9.625,4.75) 47(9.625,5.25) 48(9.625,5.75)
SOT23_2
  rect 0.9x0.83 smd: 1(-1,0.95) 2(-1,-0.95) 3(1,0)
SOT-23-3P
  rect 1.016x1.016 smd: 1(1.143,-0.889) 2(1.143,0.889) 3(-1.143,0)
SOT-23-6P
  rect 1.067x0.559 smd: 1(1.359,-0.95) 2(1.359,0) 3(1.359,0.95) 4(-1.359,0.95) 5(-1.359,0) 6(-1.359,-0.95)
SOT-223-4P
  rect 1.524x1.143 smd: 1(3.15,-2.301) 2(3.15,0) 3(3.15,2.301)
  rect 1.981x3.81 smd: 4(-3.15,0)
TP_25
  round 0.635 smd: 1(0,0)
TP_050M
  round 1 hole 0.5: 1(0,0)
TP_SMD
  round 1 smd: 1(0,0)
unnamed#2
  round 3.404 hole 3.404 unplated: (0,0)
USB-11153S1-13_6X14
  round 1.295 hole 0.991: 1(3.5,-5.911) 2(1.001,-5.911) 3(-1.001,-5.911) 4(-3.5,-5.911)
  round 2.718 hole 2.108: 5(-6.449,-3.2) 6(6.449,-3.2)
XL_HC_49U
  round 1 hole 0.6: 1(0.1,0) 2(4.98,0)
XP_2X1_100
  rect 1.6x1.6 hole 1: 1(0,0)
  round 1.6 hole 1: 2(2.54,0)
XP_HDMI_SMT
  rect 0.28x2.6 smd: 1(0,0) 2(-0.5,0) 3(-1,0) 4(-1.5,0) 5(-2,0) 6(-2.5,0) 7(-3,0) 8(-3.5,0) 9(-4,0) 10(-4.5,0) 11(-5,0) 12(-5.5,0) 13(-6,0) 14(-6.5,0) 15(-7,0) 16(-7.5,0) 17(-8,0) 18(-8.5,0) 19(-9,0)
  oval 1.9x3.7 hole 0.9x2.7: SH1(-11.75,-0.8) SH4(2.75,-0.8)
  oval 1.9x3.1 hole 0.9x2.1: SH2(-11.75,-6.8) SH3(2.75,-6.8)
XS_AV3_RCA_314
  rect 2x3 hole 2x3 unplated: (-2.55,3.4) (38.05,3.4)
  round 3 hole 1.5: A1(0,-0.2) B1(14,-0.2) C1(28,-0.2)
  round 2 hole 1.3: A2(0,7.2) B2(14,7.2) C2(28,7.2)
XS_DC_2_0
  rect 2.4x5.1 hole 1x3.2: 1(0,0) 3(-6.4,0)
  rect 5.1x2.4 hole 3.2x1: 2(-3,-4.7)
XS_DLT1150
  rect 1.4x1.4 hole 0.8: 1(0,0)
  round 1.4 hole 0.8: 2(2.54,0) 3(5.08,0)
  round 1.6 hole 1: SH1(5.08,2.51) SH2(0,2.51)
XS_SD_2041353_4
  round 1.5 hole 1.5 unplated: (-18.98,-24.55) (5.22,-24.55)
  rect 1x2 smd: 1(0,0) 2(-2.5,0) 3(-5.8,0) 4(-7.5,0) 5(-10,0) 6(-12.5,0) 7(-14.93,0) 8(-16.63,0) 9(2.5,0) 10(-4.15,0) 11(-19.98,0)
  rect 1.7x2 smd: SH1(-20.73,-22.45) SH2(7.77,-21.25)
XS_USB_AF_4P
  rect 1.52x1.52 hole 0.92: 1(0,0)
  round 1.52 hole 0.92: 2(2,0) 3(4,0) 4(6,0)
  round 2 hole 1.4: 5(-0.5,-2.9) 6(6.5,-2.9) 7(-0.5,2.9) 8(6.5,2.9)

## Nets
1V0\G: D6.2(K) L1.2 L3.2 L25.1 TP11.1
1V0_CTRL\G: C2.1 C3.1 C6.1 C8.1 C9.1 C10.1 C11.1 C13.1 C14.1 C16.1 C17.1 C23.1 C42.1 C177.1 IC13.AA14(DVDD10_1) IC13.AB25(DVDD10_2) IC13.AC14(DVDD10_3) IC13.AC25(DVDD10_4) IC13.AD14(DVDD10_5) IC13.AD25(DVDD10_6) IC13.AE15(DVDD10_7) IC13.AE16(DVDD10_8) IC13.AE17(DVDD10_9) IC13.AE19(DVDD10_10) IC13.AE20(DVDD10_11) IC13.AE22(DVDD10_12) IC13.AE23(DVDD10_13) IC13.AE24(DVDD10_14) IC13.P19(DVDD10_15) IC13.P20(DVDD10_16) IC13.P22(DVDD10_17) IC13.P23(DVDD10_18) IC13.P24(DVDD10_19) IC13.R25(DVDD10_20) IC13.T25(DVDD10_21) IC13.U14(DVDD10_22) IC13.U25(DVDD10_23) IC13.V14(DVDD10_24) IC13.W25(DVDD10_25) IC13.Y25(DVDD10_26) L5.2 L8.2 L14.2 L24.2 L25.2 L35.1 L37.2
1V5_DDR3\G: C441.1 C442.1 C443.1 C444.1 C445.1 C446.1 C447.1 C448.1 C449.1 C450.1 C451.1 C452.1 C453.1 C454.1 C455.1 C456.1 C457.1 C458.1 C459.1 C460.1 C464.1 C468.1 C472.1 C476.1 C477.1 C479.1 C480.1 C481.1 C482.1 C483.1 C484.1 C485.1 C486.1 C487.1 C488.1 C489.1 C490.1 C491.1 C492.1 C493.1 C494.1 C495.1 C496.1 C497.1 L38.2 L45.1 R619.2 R622.2 R625.2 R626.2 R629.2 R636.2 R640.2 R641.2 R644.2 R646.2 U9.A1(VDDQ1) U9.A8(VDDQ2) U9.B2(VDD1) U9.C1(VDDQ3) U9.C9(VDDQ4) U9.D2(VDDQ5) U9.D9(VDD2) U9.E9(VDDQ6) U9.F1(VDDQ7) U9.G7(VDD3) U9.H2(VDDQ8) U9.H9(VDDQ9) U9.K2(VDD4) U9.K8(VDD5) U9.N1(VDD6) U9.N9(VDD7) U9.R1(VDD8) U9.R9(VDD9) U10.A1(VDDQ1) U10.A8(VDDQ2) U10.B2(VDD1) U10.C1(VDDQ3) U10.C9(VDDQ4) U10.D2(VDDQ5) U10.D9(VDD2) U10.E9(VDDQ6) U10.F1(VDDQ7) U10.G7(VDD3) U10.H2(VDDQ8) U10.H9(VDDQ9) U10.K2(VDD4) U10.K8(VDD5) U10.N1(VDD6) U10.N9(VDD7) U10.R1(VDD8) U10.R9(VDD9)
1V5_DDR3_PHY\G: C275.1 C276.1 C277.1 C278.1 C279.1 C280.1 C281.1 C282.1 C283.1 C284.1 C285.1 C286.1 C287.1 C289.1 C290.1 C291.1 C292.1 C293.1 C295.1 C296.1 C298.1 C299.1 C300.1 C301.1 C302.1 C303.1 C304.1 C305.1 C306.1 C310.1 C311.1 C312.1 C313.1 C314.1 IC13.AD35(DDR_DVDDIF33) IC13.AD36(DDR_DVDDIF34) IC13.AG35(DDR_DVDDIF29) IC13.AG36(DDR_DVDDIF30) IC13.AM35(DDR_DVDDIF31) IC13.AN36(DDR_DVDDIF32) IC13.C17(DDR_DVDDIF35) IC13.C20(DDR_DVDDIF36) IC13.C30(DDR_DVDDIF37) IC13.D17(DDR_DVDDIF38) IC13.D20(DDR_DVDDIF39) IC13.D23(DDR_DVDDIF40) IC13.D30(DDR_DVDDIF41) IC13.E34(DDR_DVDDIF1) IC13.E35(DDR_DVDDIF2) IC13.E36(DDR_DVDDIF3) IC13.E37(DDR_DVDDIF4) IC13.E38(DDR_DVDDIF5) IC13.F34(DDR_DVDDIF6) IC13.F35(DDR_DVDDIF7) IC13.F36(DDR_DVDDIF8) IC13.K20(DDR_DVDDIF42) IC13.K21(DDR_DVDDIF43) IC13.K23(DDR_DVDDIF44) IC13.K24(DDR_DVDDIF45) IC13.K26(DDR_DVDDIF46) IC13.K27(DDR_DVDDIF47) IC13.K35(DDR_DVDDIF9) IC13.K36(DDR_DVDDIF10) IC13.K37(DDR_DVDDIF11) IC13.L20(DDR_DVDDIF48) IC13.L24(DDR_DVDDIF49) IC13.L27(DDR_DVDDIF50) IC13.M28(DDR_DVDDIF12) IC13.M29(DDR_DVDDIF13) IC13.M35(DDR_DVDDIF14) IC13.M36(DDR_DVDDIF15) IC13.N29(DDR_DVDDIF16) IC13.P29(DDR_DVDDIF17) IC13.T28(DDR_DVDDIF18) IC13.T29(DDR_DVDDIF19) IC13.T35(DDR_DVDDIF20) IC13.T36(DDR_DVDDIF21) IC13.U28(DDR_DVDDIF22) IC13.U29(DDR_DVDDIF23) IC13.V35(DDR_DVDDIF24) IC13.W28(DDR_DVDDIF25) IC13.W29(DDR_DVDDIF26) IC13.Y29(DDR_DVDDIF27) IC13.Y35(DDR_DVDDIF28) L45.2 R191.1 R196.2 R198.1 R283.2
1V8A\G: C114.1 C134.1 IC8.2(VDDPLL_1.8)
2V5\G: C32.1 C100.1 C353.1 C383.1 C384.1 L10.2 Q7.2(SOURCE) R6.2 R86.2 R108.1 R178.1 TP16.1
2V5_MOS\G: C416.1 C417.2 L6.2 L16.2 L34.1 L50.1 Q7.3(DRAIN) R6.1
3V3\G: C18.1 C33.1 C45.2 C124.1 C297.1 C381.1 C382.1 D5.1(A) L7.2 L20.2 Q6.2(SOURCE) R5.2 R43.2 R47.2 R68.1 R84.2 R120.1 R135.2 R166.1 R230.2 R357.1(A) TP29.1 U13.3(IN)
3V3_MOS\G: C1.1 C4.1 C5.2 C12.1 C15.1 C22.1 C38.1 C39.2 C106.1 C122.1 C125.1 C128.1 C130.1 C131.1 C132.1 C133.1 C135.1 C138.1 C139.1 C142.1 C143.2 C144.1 C145.1 C147.1 C149.2 C150.1 C154.1 C155.1 C156.1 C208.1 C209.1 C406.2 C407.2 C408.1 C409.1 C410.1 C411.1 FB4.2 IC2.12(VDD[0]) IC2.37(VDD[1]) IC8.17(VDDIO_3.3) IC13.AC3(DVDD33_1) IC13.AC4(DVDD33_2) IC13.AC28(DVDD33_3) IC13.AC29(DVDD33_4) IC13.AD10(DVDD33_5) IC13.AD11(DVDD33_6) IC13.AD28(DVDD33_7) IC13.AD29(DVDD33_8) IC13.AF10(DVDD33_9) IC13.AF11(DVDD33_10) IC13.AF28(DVDD33_11) IC13.AF29(DVDD33_12) IC13.AG10(DVDD33_13) IC13.AG11(DVDD33_14) IC13.AG29(DVDD33_15) IC13.AH18(DVDD33_16) IC13.AH21(DVDD33_17) IC13.AH22(DVDD33_18) IC13.AH26(DVDD33_19) IC13.AH27(DVDD33_20) IC13.AJ18(DVDD33_21) IC13.AJ21(DVDD33_22) IC13.AJ22(DVDD33_23) IC13.AJ26(DVDD33_24) IC13.AJ27(DVDD33_25) IC13.AJ28(DVDD33_26) IC13.AN35(VCC33_OTP) IC13.AP5(DVDD33_27) IC13.AP6(DVDD33_28) IC13.AP34(DVDD33_29) IC13.AP35(DVDD33_30) IC13.AR19(DVDD33_31) IC13.AR26(DVDD33_32) IC13.AR31(DVDD33_33) IC13.AT31(DVDD33_34) IC13.AU31(DVDD33_35) IC13.AV31(DVDD33_36) IC13.C10(DVDD33_37) IC13.D10(DVDD33_38) IC13.D13(DVDD33_39) IC13.D14(DVDD33_40) IC13.E5(DVDD33_41) IC13.F3(DVDD33_42) IC13.F4(DVDD33_43) IC13.F5(DVDD33_44) IC13.K10(DVDD33_45) IC13.K12(DVDD33_46) IC13.K13(DVDD33_47) IC13.L10(DVDD33_48) IC13.L11(DVDD33_49) IC13.L13(DVDD33_50) IC13.M11(DVDD33_51) IC13.U3(DVDD33_52) IC13.U4(DVDD33_53) IC13.U10(DVDD33_54) IC13.U11(DVDD33_55) IC13.V11(DVDD33_56) JP1.1 L19.1 L21.1 L22.1 L23.2 L36.1 LED5.1(A) Q6.3(DRAIN) R5.1 R37.2 R38.2 R39.2 R41.2 R45.2 R49.2 R52.2 R54.2 R83.2 R91.2 R94.2 R96.2 R97.2 R98.2 R99.2 R101.2 R111.2 R118.2 R138.2 R139.1 R144.2 R153.2 R167.2 R168.2 R170.2 R222.2 R223.2 R224.2 R225.2 R233.2 R244.2 R245.2 R248.2 R251.2 R293.2 R298.2 R313.1 R314.1 R475.1 R586.1 R589.1 R605.1 R606.1 R608.1 R609.1 R611.1 R612.1 R614.1 R615.1 U1.9(VDD33_1) U1.20(VDD33_2) U1.30(VDD33_3) U1.48(VDD33REG) U11.8(VCC)
3V3A_E\G: C136.2 C137.2 C153.2 C160.2 IC8.3(VDDA_3.3) L19.2 TR2.2(CT0) TR2.7(CT1) U17.5
5V0\G: C85.2 C88.2 L12.2 Q5.2(SOURCE) Q8.2(SOURCE) Q10.2(SOURCE) R4.2 R78.2 R105.1 R110.1 R119.1 R255.2 R331.2 R509.1
5V0_MOS\G: C96.1 C123.2 C251.1 C426.1 C427.1 C429.1 C430.1 C433.1 C434.1 C437.1 C438.1 D20.2 L41.2 L47.1 Q5.3(DRAIN) Q9.2(SOURCE) R4.1 R8.2 R140.2 R141.2 R165.2 R174.1(A) R368.2 R472.1 R474.1 R632.2 R633.2 R649.2 R650.2 U3.5 U4.5 U5.7(IN) U6.7(IN) U7.7(IN) U8.7(IN) U14.5 XP1.18 XS7.2
5V0_VBUS0\G: C78.2 C82.2 L55.2 Q8.3(DRAIN) R105.2
5V0_VBUS1\G: C91.2 C95.2 L56.2 Q10.3(DRAIN) R110.2
5V_VIDEO\G: C84.1 C102.1 C176.1 D16.2 IC9.4(VCC) L41.1
12V\G: C43.2 C44.2 C49.2 C50.2 C51.2 C52.2 C77.2 C79.2 C80.2 C81.2 C98.2 C111.2 C112.2 C121.2 C126.1 C127.2 IC5.13(VIN1) IC5.14(VIN2) IC12.2(IN) IC14.2(IN) IC17.2(IN) IC26.13(VIN1) IC26.14(VIN2) L18.2 LED1.1(A) R51.2 R100.1 R123.2 R124.2 R134.2 TP6.1
+1V2: C254.1 C317.1 C318.1 C321.1 C328.1 C331.1 C335.1 C343.1 C360.1 C379.1 FB1.2 L43.2 R318.1 R348.1 R352.1 U18.7(VDD_1) U18.12(VDD_2) U18.51(VDD_3) U18.53(VDD_4) U18.61(TVDD) U18.64(PVDD) U18.67(RVDD)
+1V2A: C319.2 R346.2 U24.2(OUT)
GND: ANT1.2 ANT1.3 ANT1.4 ANT2.2 ANT2.3 ANT2.4 ANT3.2 ANT3.3 ANT3.4 ANT4.2 ANT4.3 ANT4.4 ANT5.2 ANT6.2 C1.2 C2.2 C3.2 C4.2 C5.1 C6.2 C7.2 C8.2 C9.2 C10.2 C11.2 C12.2 C13.2 C14.2 C15.2 C16.2 C17.2 C18.2 C19.2 C20.1 C21.2 C22.2 C23.2 C24.2 C25.1 C26.1 C27.2 C28.1 C29.2 C30.2 C31.1 C32.2 C33.2 C35.1 C37.2 C38.2 C39.1 C40.1 C41.1 C42.2 C43.1 C44.1 C45.1 C46.1 C47.2 C48.2 C49.1 C50.1 C51.1 C52.1 C53.2(B) C56.1 C57.1 C58.2 C59.2 C61.1 C63.2 C67.1 C72.2 C75.2(B) C77.1 C78.1 C79.1 C80.1 C81.1 C82.1 C84.2 C86.2 C90.2 C91.1 C94.1 C95.1 C96.2 C98.1 C100.2 C102.2 C106.2 C107.1 C108.2 C109.1 C110.2 C111.1 C112.1 C113.1 C114.2 C115.2 C117.2 C118.2 C119.1 C121.1 C122.2 C123.1 C124.2 C125.2 C126.2 C127.1 C128.2 C130.2 C131.2 C132.2 C133.2 C134.2 C135.2 C136.1 C137.1 C138.2 C139.2 C142.2 C143.1 C144.2 C145.2 C146.2 C147.2 C148.2 C149.1 C150.2 C151.1 C152.1 C153.1 C154.2 C155.2 C156.2 C157.2 C158.2 C159.2 C160.1 C161.1 C162.2 C163.1 C167.2 C169.1 C171.1 C173.2 C174.2 C175.2 C176.2 C177.2 C178.2 C180.1 C181.2 C182.2 C186.1 C196.1 C197.2 C198.1 C199.2 C200.1 C201.1 C202.1 C203.2 C205.1 C207.1 C208.2 C209.2 C210.2 C211.2 C212.1 C213.2 C214.2 C215.2 C216.2 C217.2 C218.2 C219.2 C220.2 C221.2 C222.1 C223.2 C224.2 C225.2 C226.2 C227.2 C229.2 C230.2 C231.2 C232.2 C233.2 C234.2 C235.2 C236.2 C237.2 C239.2 C241.2 C242.2 C243.1 C244.2 C245.2 C246.2 C247.2 C248.2 C249.1 C250.2 C251.2 C254.2 C255.1 C272.2 C274.2 C275.2 C276.2 C277.2 C278.2 C279.2 C280.2 C281.2 C282.2 C283.2 C284.2 C285.2 C286.2 C287.2 C288.1 C289.2 C290.2 C291.2 C292.2 C294.2 C295.2 C296.2 C297.2 C298.2 C299.2 C300.2 C301.2 C302.2 C303.2 C304.2 C305.2 C306.2 C307.2(C) C308.1 C309.1 C310.2 C311.2 C312.2 C313.2 C315.2 C316.2 C317.2 C318.2 C319.1 C320.2 C321.2 C322.2 C323.2 C325.1 C326.2 C328.2 C329.1 C330.2 C331.2 C333.2 C336.2 C337.1 C338.2(B) C339.1 C340.2 C341.2 C342.2 C343.2 C344.1 C345.2 C346.2 C347.1 C348.2 C351.2 C352.2 C353.2 C354.2 C355.1 C360.2 C361.1 C362.2 C363.2 C364.2 C365.2 C366.1 C367.2 C368.2 C369.2 C370.2 C371.1 C374.2 C375.2 C376.2 C377.2 C378.2 C379.2 C380.2 C381.2 C382.2 C383.2 C384.2 C385.2 C386.2 C388.2 C389.2 C391.2(B) C392.1 C394.1 C404.2 C405.2 C406.1 C407.1 C408.2 C409.2 C410.2 C411.2 C412.1 C415.2 C416.2 C417.1 C418.2 C419.2 C420.2 C421.2 C422.2 C423.2 C424.2 C425.2 C426.2 C427.2 C428.2 C429.2 C430.2 C431.2 C432.2 C433.2 C434.2 C435.2 C436.2 C437.2 C438.2 C439.2 C441.2 C442.2 C443.2 C444.2 C445.2 C446.2 C447.2 C448.2 C449.2 C450.2 C451.2 C452.2 C453.2 C454.2 C455.2 C456.2 C457.2 C458.2 C459.2 C460.2 C461.2 C462.2 C463.2 C465.2 C466.2 C467.2 C469.2 C470.2 C471.2 C473.2 C474.2 C475.2 C476.2 C477.2 C478.2 C479.2 C480.2 C482.2 C483.2 C484.2 C485.2 C486.2 C487.2 C488.2 C489.2 C490.2 C491.2 C492.2 C493.2 C494.2 C495.2 C496.2 C497.2 C0603.2 CAP3.2(C) D10.1 D11.1 D16.1 D20.1 D37.2(GND) IC2.13(VSS[0]) IC2.36(VSS[1]) IC5.5(GND) IC5.8(PGND1) IC5.9(PGND2) IC5.15(EXPAD) IC8.1(GND) IC8.33(EXPAD) IC9.5(GND) IC12.4(GND) IC13.A1(VSS1) IC13.A8(VSS2) IC13.A31(VSS3) IC13.A35(VSS4) IC13.A38(VSS5) IC13.AA15(VSS6) IC13.AA16(VSS7) IC13.AA17(VSS8) IC13.AA18(VSS9) IC13.AA19(VSS10) IC13.AA20(VSS11) IC13.AA21(VSS12) IC13.AA22(VSS13) IC13.AA23(VSS14) IC13.AA24(VSS15) IC13.AA25(VSS16) IC13.AA28(VSS17) IC13.AA29(VSS18) IC13.AB11(AVSS_QAM1) IC13.AB14(VSS19) IC13.AB15(VSS20) IC13.AB16(VSS21) IC13.AB17(VSS22) IC13.AB18(VSS23) IC13.AB19(VSS24) IC13.AB20(VSS25) IC13.AB21(VSS26) IC13.AB22(VSS27) IC13.AB23(VSS28) IC13.AB24(VSS29) IC13.AB37(VSS30) IC13.AB38(VSS31) IC13.AC10(AVSS_QAM2) IC13.AC15(VSS32) IC13.AC16(VSS33) IC13.AC17(VSS34) IC13.AC18(VSS35) IC13.AC19(VSS36) IC13.AC20(VSS37) IC13.AC21(VSS38) IC13.AC22(VSS39) IC13.AC23(VSS40) IC13.AC24(VSS41) IC13.AC35(VSS42) IC13.AC36(VSS43) IC13.AD3(VSS44) IC13.AD4(VSS45) IC13.AD15(VSS46) IC13.AD16(VSS47) IC13.AD17(VSS48) IC13.AD18(VSS49) IC13.AD19(VSS50) IC13.AD20(VSS51) IC13.AD21(VSS52) IC13.AD22(VSS53) IC13.AD23(VSS54) IC13.AD24(VSS55) IC13.AE2(VSS56) IC13.AE10(VSS57) IC13.AE11(VSS58) IC13.AE14(VSS59) IC13.AE18(VSS60) IC13.AE21(VSS61) IC13.AE25(VSS62) IC13.AE28(VSS63) IC13.AE29(VSS64) IC13.AE35(VSS65) IC13.AF2(VSS66) IC13.AF3(VSS67) IC13.AF4(VSS68) IC13.AF35(VSS69) IC13.AG28(VSS70) IC13.AH3(VSS71) IC13.AH4(VSS72) IC13.AH11(AGND_ADAC_1) IC13.AH12(AGND_VDAC0_1) IC13.AH13(AGND_VDAC0_2) IC13.AH17(AGND_VDAC1_1) IC13.AH19(AVSS_HDMI_1) IC13.AH23(VSS73) IC13.AH24(AVSS_USB1) IC13.AH28(VSS74) IC13.AH29(VSS75) IC13.AH37(VSS76) IC13.AH38(VSS77) IC13.AJ11(AGND_ADAC_2) IC13.AJ12(AGND_VDAC0_3) IC13.AJ16(AGND_VDAC1_2) IC13.AJ17(AGND_VDAC1_3) IC13.AJ19(AVSS_HDMI_2) IC13.AJ23(VSS78) IC13.AJ24(AVSS_USB2) IC13.AJ25(DVSS_USB) IC13.AJ29(VSS79) IC13.AJ35(VSS80) IC13.AJ36(VSS81) IC13.AK4(VSS82) IC13.AL3(AVSS_QAM3) IC13.AL4(AVSS_QAM4) IC13.AM3(AVSS_QAM5) IC13.AM4(AVSS_QAM6) IC13.AN5(VSS83) IC13.AP4(VSS84) IC13.AP33(VSS85) IC13.AR7(AGND_ADAC_3) IC13.AR9(ADAC_AGNDREF) IC13.AR11(AGND_VDAC0_4) IC13.AR12(AGND_VDAC1_4) IC13.AR13(AGND_VDAC1_5) IC13.AR17(VSS86) IC13.AR20(AVSS_HDMI_3) IC13.AR23(AVSS_HDMI_4) IC13.AR25(VSS87) IC13.AR28(AVSS_USB3) IC13.AR29(AVSS_USB4) IC13.AR32(VSS88) IC13.AR33(VSS89) IC13.AR34(VSS90) IC13.AR35(VSS91) IC13.AT7(AGND_ADAC_4) IC13.AT10(AGND_VDAC0_5) IC13.AT14(AGND_VDAC1_6) IC13.AT17(VSS92) IC13.AT20(AVSS_HDMI_5) IC13.AT23(AVSS_HDMI_6) IC13.AT29(AVSS_USB5) IC13.AU8(AGND_ADAC_5) IC13.AU11(AGND_VDAC0_6) IC13.AU13(AGND_VDAC1_7) IC13.AU37(VSS93) IC13.AV1(VSS94) IC13.AV38(VSS95) IC13.B8(VSS96) IC13.B22(VSS97) IC13.B31(VSS98) IC13.B35(VSS99) IC13.C7(VSS100) IC13.C15(VSS101) IC13.C19(VSS102) IC13.C22(VSS103) IC13.C28(VSS104) IC13.C34(VSS105) IC13.D7(VSS106) IC13.D11(VSS107) IC13.D12(VSS108) IC13.D15(VSS109) IC13.D16(VSS110) IC13.D19(VSS111) IC13.D22(VSS112) IC13.D24(VSS113) IC13.D28(VSS114) IC13.D34(VSS115) IC13.E6(VSS116) IC13.E33(VSS117) IC13.G4(VSS118) IC13.G35(VSS119) IC13.H4(VSS120) IC13.H35(VSS121) IC13.H36(VSS122) IC13.K1(VSS123) IC13.K2(VSS124) IC13.K11(VSS125) IC13.K18(VSS126) IC13.K19(VSS127) IC13.K22(VSS128) IC13.K25(VSS129) IC13.K28(VSS130) IC13.L3(VSS131) IC13.L4(VSS132) IC13.L12(VSS133) IC13.L14(VSS_PLL5) IC13.L15(VSS_PLL_1) IC13.L16(VSS_PLL_2) IC13.L18(VSS134) IC13.L19(VSS135) IC13.L22(VSS136) IC13.L25(VSS137) IC13.L29(VSS138) IC13.L35(VSS139) IC13.M10(VSS140) IC13.N3(VSS141) IC13.N4(VSS142) IC13.N11(VSS143) IC13.N37(VSS144) IC13.P1(VSS145) IC13.P2(VSS146) IC13.P3(VSS147) IC13.P4(VSS148) IC13.P14(VSS149) IC13.P18(VSS150) IC13.P21(VSS151) IC13.P25(VSS152) IC13.P28(VSS153) IC13.P35(VSS154) IC13.P36(VSS155) IC13.R14(VSS156) IC13.R15(VSS157) IC13.R16(VSS158) IC13.R17(VSS159) IC13.R18(VSS160) IC13.R19(VSS161) IC13.R20(VSS162) IC13.R21(VSS163) IC13.R22(VSS164) IC13.R23(VSS165) IC13.R24(VSS166) IC13.R29(VSS167) IC13.T10(VSS168) IC13.T14(VSS169) IC13.T15(VSS170) IC13.T16(VSS171) IC13.T17(VSS172) IC13.T18(VSS173) IC13.T19(VSS174) IC13.T20(VSS175) IC13.T21(VSS176) IC13.T22(VSS177) IC13.T23(VSS178) IC13.T24(VSS179) IC13.U15(VSS180) IC13.U16(VSS181) IC13.U17(VSS182) IC13.U18(VSS183) IC13.U19(VSS184) IC13.U20(VSS185) IC13.U21(VSS186) IC13.U22(VSS187) IC13.U23(VSS188) IC13.U24(VSS189) IC13.U35(VSS190) IC13.V10(VSS191) IC13.V15(VSS192) IC13.V16(VSS193) IC13.V17(VSS194) IC13.V18(VSS195) IC13.V19(VSS196) IC13.V20(VSS197) IC13.V21(VSS198) IC13.V22(VSS199) IC13.V23(VSS200) IC13.V24(VSS201) IC13.V25(VSS202) IC13.V28(VSS203) IC13.V29(VSS204) IC13.W11(VSS205) IC13.W14(VSS206) IC13.W15(VSS207) IC13.W16(VSS208) IC13.W17(VSS209) IC13.W18(VSS210) IC13.W19(VSS211) IC13.W20(VSS212) IC13.W21(VSS213) IC13.W22(VSS214) IC13.W23(VSS215) IC13.W24(VSS216) IC13.W35(VSS217) IC13.Y3(VSS218) IC13.Y4(VSS219) IC13.Y14(VSS220) IC13.Y15(VSS221) IC13.Y16(VSS222) IC13.Y17(VSS223) IC13.Y18(VSS224) IC13.Y19(VSS225) IC13.Y20(VSS226) IC13.Y21(VSS227) IC13.Y22(VSS228) IC13.Y23(VSS229) IC13.Y24(VSS230) IC14.4(GND) IC17.4(GND) IC17.9 IC26.5(GND) IC26.8(PGND1) IC26.9(PGND2) IC26.15(EXPAD) JP1.4 L26.1 L31.1 L39.1 L40.1 L42.1 L44.1 L49.1 R12.1 R17.2 R36.2 R40.2 R42.2 R44.2 R46.2 R48.2 R50.1 R53.1 R55.1 R56.1 R67.2 R71.2 R72.2 R73.2 R74.1 R75.1 R76.1 R77.1 R79.2 R80.2 R85.1 R92.2 R93.1 R95.2 R102.1 R104.2 R106.1 R109.2 R113.2 R115.1 R116.2 R117.1 R121.2 R122.2 R133.2 R138.1 R145.1 R146.2 R155.2 R169.1 R171.1 R172.1 R173.1 R175.2 R176.2 R177.2 R188.1 R190.2 R192.2 R194.2 R195.2 R197.2 R199.2 R226.1 R227.2 R228.2 R229.2 R246.2(B) R249.2 R250.2 R253.2 R256.1(A) R258.1(A) R276.2 R290.1 R295.2 R297.2 R299.1 R300.1 R311.1 R312.1 R329.2 R340.2 R342.1 R350.1 R354.1 R360.2 R362.2 R366.2 R367.2 R458.2 R567.2 R583.2 R584.2 R588.1 R600.2 R607.2 R610.2 R613.2 R616.2 R618.1 R623.1 R624.1 R627.1 R628.1 R634.1 R635.1 R639.1 R642.1 R643.1 R648.1 T2.2(E) T3.2(E) T4.2(E) T5.2(E) T6.2(E) T7.2(E) T8.2(E) T9.2(E) TP7.1 TP20.1 U1.2(VSSREG) U1.23(VSS1) U1.27(VSS2) U1.36(VSS3) U1.42(VSS4) U2.2(GND1) U2.4(GND2) U3.2 U4.2 U5.3(GND) U6.3(GND) U7.3(GND) U8.3(GND) U9.A9(VSS1) U9.B1(VSSQ1) U9.B3(VSS2) U9.B9(VSSQ2) U9.D1(VSSQ3) U9.D8(VSSQ4) U9.E1(VSS3) U9.E2(VSSQ5) U9.E8(VSSQ6) U9.F9(VSSQ7) U9.G1(VSSQ8) U9.G8(VSS4) U9.G9(VSSQ9) U9.J2(VSS5) U9.J8(VSS6) U9.M1(VSS7) U9.M9(VSS8) U9.P1(VSS9) U9.P9(VSS10) U9.T1(VSS11) U9.T9(VSS12) U10.A9(VSS1) U10.B1(VSSQ1) U10.B3(VSS2) U10.B9(VSSQ2) U10.D1(VSSQ3) U10.D8(VSSQ4) U10.E1(VSS3) U10.E2(VSSQ5) U10.E8(VSSQ6) U10.F9(VSSQ7) U10.G1(VSSQ8) U10.G8(VSS4) U10.G9(VSSQ9) U10.J2(VSS5) U10.J8(VSS6) U10.M1(VSS7) U10.M9(VSS8) U10.P1(VSS9) U10.P9(VSS10) U10.T1(VSS11) U10.T9(VSS12) U11.4(GND) U12.3(P3) U12.6(P6) U12.SH1(S1) U12.SH2(S2) U14.2 U15.3(GND1) U15.8(GND) U16.3(GND1) U16.8(GND) U17.2 U18.17(NC_0) U18.69(GND) U19.2(GND) U20.1(GND) U21.2(GND) U22.1(+INR) U22.4(SGND) U22.10(PGND) U22.14(+INL) U23.5(GND) U23.7(PAD) U24.1(GND) XP1.2 XP1.5 XP1.8 XP1.11 XP1.17 XP1.SH1 XP1.SH2 XP1.SH3 XP1.SH4 XS1.4(GND) XS1.5(SHD1) XS1.6(SHD2) XS2.2 XS2.3 XS4.4(GND) XS4.5(SHD1) XS4.6(SHD2) XS4.7(SHD3) XS4.8(SHD4) XS5.4(GND) XS5.5(SHD1) XS5.6(SHD2) XS5.7(SHD3) XS5.8(SHD4) XS7.1 XS7.SH1 XS7.SH2 XS9.A1 XS9.B1 XS9.C1 XS10.4(GND) XS10.5(SHD1) XS10.6(SHD2) Y4.2(GND#2) Y4.4(GND#4)
VCC_3.3V: C210.1 C211.1 C218.1 C244.1 C245.1 C246.1 C316.1 C330.1 C333.1 C339.2 C342.1 C345.1 C362.1 C363.1 C364.1 C368.1 C369.1 C370.1 C371.2 C378.1 FB4.1 R29.2 R320.1 R321.1 R335.1 R338.2 R344.1 U18.6(VDDIO_OTP_VDD) U18.19(PA_2G_CORE1_VDD3P3) U18.20(PAD_2G_CORE1_VDD3P3) U18.30(PAD_2G_CORE0_VDD3P3) U18.31(PA_2G_CORE0_VDD3P3) U18.49(VDDIO_1) U18.56(VDDIO_2) U18.68(VDDIO_3) U23.2(EN) U23.3(VIN) U24.3(VIN)
VCC_SCI\G: C146.1 C148.1 Q9.3(DRAIN) R8.1 R147.2 R148.2 R149.2 R150.2 R151.2 R152.2 R290.2 U12.4(P4)
VDD1_2_RF_LDO: C248.1 FB2.1 FB3.1 R326.1 R333.2 R346.1 R353.1
VDD25OUT: C412.2 C415.1 C419.1 C420.1 C421.1 L48.1 L50.2 U1.1(VDD25OUT) U1.12(VDD25_1) U1.24(VDD25_2) U1.33(VDD25_3)
VDD_AUDIO: C75.1(A) C203.1 R174.2(B) R247.2(B) U22.9(PVDD)
VDDPLL: C340.1 R326.2 U18.43(VDDPLL)
2G_0_SW_OUT: C324.2 C377.1 R336.1 U21.5(J1)
2G_1_SW_OUT: C372.2 C375.1 R345.1 U19.5(J1)
43227_VDDIN_RFL: C336.1 R320.2 U18.45(I_VDD_RFL)
/WDG_RSTN\G: IC13.D6(WDG_RSTN) R356.1(A)
AFE_INPUT_VDD1P2: C326.1 R352.2 U18.42(VDDAFE)
AUDIO_L\G: C392.2 R257.1(A) XS9.B2
AUDIO_OUTL\G: C268.1(A) IC13.AV7(ADAC_LINEOUTL) R175.1
AUDIO_OUTR\G: C393.2(B) IC13.AV8(ADAC_LINEOUTR) R362.1
AUDIO_R\G: C394.2 R361.2(B) XS9.C2
AVS_VREF_IO\G: C87.2 C90.1 R15.1
BOOT_SEL0\G: IC13.AB4(NF_CLE/BOOT_SEL0) R39.1 R40.1 R58.2
BOOT_SEL1\G: IC13.AA4(NF_ALE/BOOT_SEL1) R57.2 R83.1 R155.1
BSC_M0_SCL\G: D10.2 IC13.AV19(GPIO3_1/I2C1_SCL) R140.1 U14.3 XP1.15
BSC_M0_SDA\G: D11.2 IC13.AU19(GPIO3_0/I2C1_SDA) R141.1 U14.4 XP1.16
CLK_50M_PHY0\G: IC8.9(XI/REFCLK) R240.2
CORE0_RX: C361.2 U18.13(MIMOPHY_CORE0_ANT0_RX) U21.6(V2)
CORE0_TX: C366.2 U18.14(MIMOPHY_CORE0_ANT0_TX) U21.4(V1)
CORE1_RX: C337.2 U18.16(MIMOPHY_CORE1_ANT0_RX) U19.4(V1)
CORE1_TX: C344.2 U18.15(MIMOPHY_CORE1_ANT0_TX) U19.6(V2)
CVBS\G: C341.1 IC9.3(IN3) IC13.AV13(VDAC1_IOUT2) R92.1 R95.1
CVBS_OUT\G: C36.2 D16.3 R163.2 XS9.A2
DDRA_ADDR0: R205.1 U9.N3(A0)
DDRA_ADDR0_R: IC13.AL38(DDRA_ADR0) R205.2
DDRA_ADDR1: R217.1 U9.P7(A1)
DDRA_ADDR1_R: IC13.AB36(DDRA_ADR1) R217.2
DDRA_ADDR2: R206.1 U9.P3(A2)
DDRA_ADDR2_R: IC13.AL37(DDRA_ADR2) R206.2
DDRA_ADDR3: R216.1 U9.N2(A3)
DDRA_ADDR3_R: IC13.AE36(DDRA_ADR3) R216.2
DDRA_ADDR4: R210.1 U9.P8(A4)
DDRA_ADDR4_R: IC13.AJ38(DDRA_ADR4) R210.2
DDRA_ADDR5: R215.1 U9.P2(A5)
DDRA_ADDR5_R: IC13.AF36(DDRA_ADR5) R215.2
DDRA_ADDR6: R211.1 U9.R8(A6)
DDRA_ADDR6_R: IC13.AJ37(DDRA_ADR6) R211.2
DDRA_ADDR7: R214.1 U9.R2(A7)
DDRA_ADDR7_R: IC13.AE37(DDRA_ADR7) R214.2
DDRA_ADDR8: R209.1 U9.T8(A8)
DDRA_ADDR8_R: IC13.AK35(DDRA_ADR8) R209.2
DDRA_ADDR9: R212.1 U9.R3(A9)
DDRA_ADDR9_R: IC13.AF37(DDRA_ADR9) R212.2
DDRA_ADDR10: R218.1 U9.L7(A10/AP)
DDRA_ADDR10_R: IC13.AB35(DDRA_ADR10) R218.2
DDRA_ADDR11: R208.1 U9.R7(A11)
DDRA_ADDR11_R: IC13.AK36(DDRA_ADR11) R208.2
DDRA_ADDR12: R213.1 U9.N7(A12/BC-)
DDRA_ADDR12_R: IC13.AE38(DDRA_ADR12) R213.2
